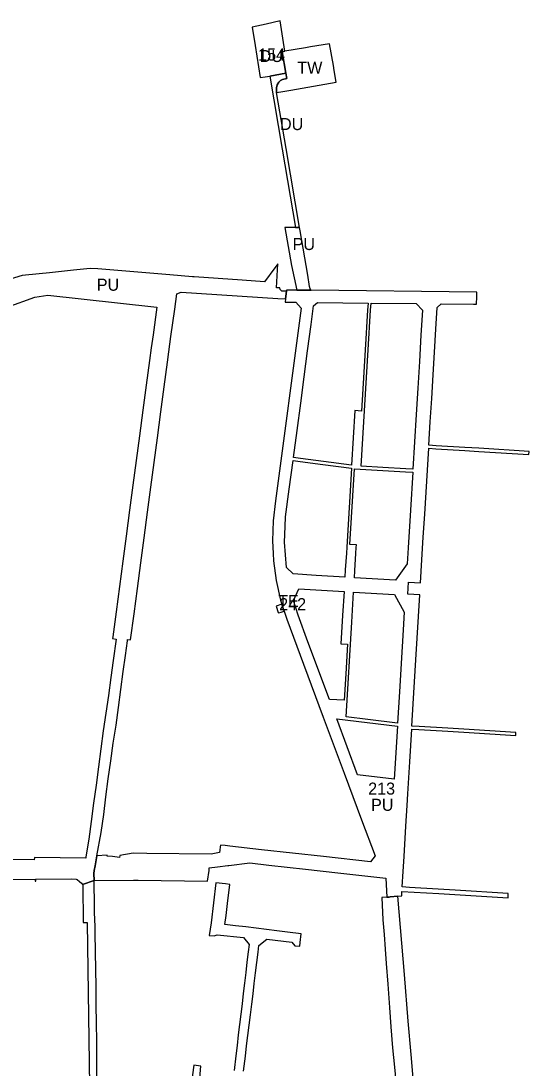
# Model space of a CAD drawing. Extents: x -521047 to -518054, y -1194945 to -1189555.
# Drawn here: x -519638 to -519216, y -1191621 to -1190751 of the extents above; entities that cross this region are included whole.
import ezdxf

# ---------------------------------------------------------------- set-up
doc = ezdxf.new("R2010")
doc.units = 0
for name, color, linetype in [('90310013', 7, 'Continuous'), ('90310023', 7, 'Continuous'), ('90390013', 7, 'Continuous'), ('90400023', 7, 'Continuous'), ('90450013', 7, 'Continuous'), ('90450023', 7, 'Continuous'), ('ID_navrh', 7, 'Continuous')]:
    doc.layers.add(name, color=color, linetype=linetype)

msp = doc.modelspace()

# ---------------------------------------------------------------- linework, layer by layer
at = {"layer": '90310013'}
msp.add_lwpolyline([(-519425.9, -1190810.59), (-519426, -1190810.03), (-519426.07, -1190806.55), (-519425.43, -1190804.16), (-519424.12, -1190802.05), (-519422.73, -1190800.6), (-519421.01, -1190799.59), (-519417.51, -1190798.76), (-519418.25, -1190794.59), (-519427.06, -1190796.08), (-519431.49, -1190796.83), (-519421.19, -1190857.53), (-519410.13, -1190922.68), (-519406.86, -1190922.67), (-519418.01, -1190857.09), (-519425.9, -1190810.59)], dxfattribs=at)
at = {"layer": '90310023'}
msp.add_lwpolyline([(-519431.49, -1190796.83), (-519427.06, -1190796.08), (-519418.25, -1190794.59), (-519421.35, -1190776.66), (-519419.09, -1190776.27), (-519423.08, -1190751.07), (-519434.67, -1190753.64), (-519446.26, -1190756.2), (-519443.82, -1190771.36), (-519439.5, -1190798.18), (-519435.5, -1190797.51), (-519431.49, -1190796.83)], dxfattribs=at)
at = {"layer": '90390013'}
msp.add_lwpolyline([(-519425.9, -1190810.59), (-519420.82, -1190809.69), (-519415.74, -1190808.8), (-519413.98, -1190808.49), (-519376.41, -1190801.97), (-519378.08, -1190792.18), (-519378.78, -1190788), (-519381.92, -1190770.01), (-519397.85, -1190772.66), (-519402.04, -1190773.36), (-519419.09, -1190776.27), (-519421.35, -1190776.66), (-519418.25, -1190794.59), (-519417.51, -1190798.76), (-519421.01, -1190799.59), (-519422.73, -1190800.6), (-519424.12, -1190802.05), (-519425.43, -1190804.16), (-519426.07, -1190806.55), (-519426, -1190810.03), (-519425.9, -1190810.59)], dxfattribs=at)
at = {"layer": '90400023'}
msp.add_lwpolyline([(-519421.48, -1191235.61), (-519426.25, -1191237.12), (-519424.56, -1191242.44), (-519424.44, -1191242.84), (-519421.98, -1191242.06), (-519419.67, -1191241.33), (-519420.1, -1191239.99), (-519421.46, -1191235.67), (-519421.48, -1191235.61)], dxfattribs=at)
at = {"layer": '90450013'}
for points in [[(-519419.2, -1190922.7), (-519413.53, -1190954.2), (-519409.21, -1190974.7), (-519397.29, -1190974.84), (-519398.04, -1190973.7), (-519398.51, -1190971.76), (-519400.11, -1190962.39), (-519406.39, -1190925.44), (-519406.86, -1190922.67), (-519410.13, -1190922.68), (-519414.66, -1190922.69), (-519419.2, -1190922.7)], [(-519417.75, -1190975.6), (-519421.6, -1190975.48), (-519423.05, -1190974.12), (-519423.35, -1190972.89), (-519426.07, -1190972.68), (-519424.76, -1190952.81), (-519427.27, -1190956.19), (-519435.92, -1190967.84), (-519454.45, -1190966.5), (-519474.45, -1190965.06), (-519494.45, -1190963.62), (-519495.64, -1190963.53), (-519514.45, -1190962), (-519534.46, -1190960.37), (-519554.46, -1190958.75), (-519574.46, -1190957.12), (-519580.63, -1190956.62), (-519594.46, -1190958.09), (-519614.46, -1190960.23), (-519634.45, -1190962.36), (-519637.19, -1190962.65), (-519654.44, -1190967.68)], [(-519734.08, -1191464.3), (-519626.5, -1191463.94), (-519626.5, -1191465.57), (-519625.81, -1191465.57), (-519625.82, -1191463.94), (-519595.86, -1191463.83), (-519592.36, -1191464.04), (-519591.42, -1191464.38), (-519589.46, -1191465.93), (-519587.99, -1191467.28), (-519586.99, -1191468.38), (-519577.51, -1191465.05), (-519577.64, -1191459.18), (-519577.4, -1191456.82), (-519576.66, -1191452.79), (-519575.16, -1191444.67), (-519571.58, -1191425.3), (-519569.46, -1191410.24), (-519567.75, -1191395.5), (-519565.7, -1191380.6), (-519563.45, -1191365.79), (-519561.62, -1191351.05), (-519559.21, -1191335.98), (-519557.24, -1191321.36), (-519555.15, -1191306.5), (-519553.19, -1191291.45), (-519551.46, -1191278.14), (-519549.81, -1191265.9), (-519549.65, -1191264.77), (-519547.09, -1191265.09), (-519544.25, -1191243.58), (-519541.47, -1191222.48), (-519538.69, -1191201.28), (-519535.92, -1191180.56), (-519533.06, -1191159.12), (-519530.29, -1191138.35), (-519527.54, -1191117.76), (-519524.82, -1191097.41), (-519521.95, -1191075.91), (-519519.18, -1191055.12), (-519516.44, -1191034.58), (-519515.29, -1191025.95), (-519513.6, -1191013.34), (-519510.54, -1190990.37), (-519508.85, -1190977.63), (-519505.2, -1190976.39), (-519424.9, -1190981.51), (-519418.57, -1190981.92), (-519417.75, -1190975.6)], [(-519649.73, -1190988.71), (-519626.59, -1190980.56), (-519615.78, -1190978.97), (-519588.06, -1190981.97), (-519525.44, -1190988.75), (-519528.51, -1191011.75), (-519529.95, -1191022.61), (-519531.36, -1191033.18), (-519534.1, -1191053.67), (-519536.85, -1191074.32), (-519539.71, -1191095.78), (-519542.44, -1191116.24), (-519543.82, -1191126.59), (-519545.18, -1191136.77), (-519547.94, -1191157.45), (-519550.81, -1191178.95), (-519553.58, -1191199.76), (-519556.38, -1191220.91), (-519559.17, -1191242.02), (-519561.89, -1191262.61), (-519562.09, -1191264.1), (-519559.08, -1191264.54), (-519561.72, -1191282.43), (-519563.63, -1191296.41), (-519565.38, -1191311.3), (-519567.65, -1191326.14), (-519569.89, -1191340.84), (-519571.87, -1191355.85), (-519573.82, -1191370.58), (-519575.84, -1191385.91), (-519577.81, -1191400.9), (-519579.89, -1191416.11), (-519581.9, -1191430.86), (-519584.36, -1191445.56), (-519584.29, -1191446.5), (-519626.81, -1191445.94), (-519627.09, -1191448.06), (-519657.04, -1191447.59)], [(-519575.11, -1191628.65), (-519575.26, -1191613.61), (-519575.26, -1191598.56), (-519575.45, -1191583.57), (-519575.65, -1191568.52), (-519575.75, -1191553.53), (-519575.99, -1191538.83), (-519576.22, -1191524.54), (-519576.49, -1191508.37), (-519576.64, -1191503.42), (-519577, -1191491.8), (-519577.15, -1191487.01), (-519577.51, -1191465.05), (-519586.99, -1191468.38), (-519586.83, -1191468.84), (-519586.55, -1191499.99), (-519583.09, -1191499.99), (-519580.83, -1191674.78)], [(-519453.36, -1191623.48), (-519451.82, -1191611.01), (-519450.78, -1191602.53), (-519449.7, -1191593.83), (-519448.57, -1191585.21), (-519447.62, -1191576.63), (-519446.55, -1191567.85), (-519445.5, -1191559.25), (-519444.45, -1191550.62), (-519443.39, -1191541.92), (-519442.33, -1191533.25), (-519441.27, -1191524.61), (-519440.6, -1191519.15), (-519433.91, -1191513.92), (-519413.38, -1191516.41), (-519410.68, -1191519.29), (-519406.71, -1191519.74), (-519406.35, -1191516.56), (-519405.54, -1191509.38), (-519416.85, -1191507.99), (-519425.59, -1191506.91), (-519434.21, -1191505.85), (-519442.74, -1191504.8), (-519451.47, -1191503.72), (-519460.11, -1191502.66), (-519468.8, -1191501.59), (-519467.9, -1191494.14), (-519466.69, -1191484.19), (-519464.87, -1191468.3), (-519468.24, -1191467.91), (-519476.39, -1191466.96), (-519480.11, -1191500.2), (-519481.79, -1191510.66), (-519477.82, -1191511.18), (-519475.17, -1191510.14), (-519453.49, -1191512.38), (-519448.78, -1191518.39), (-519449.49, -1191524.35), (-519450.51, -1191532.95), (-519451.54, -1191541.66), (-519452.56, -1191550.28), (-519453.59, -1191558.94), (-519454.62, -1191567.56), (-519455.64, -1191576.17), (-519456.67, -1191584.81), (-519457.69, -1191593.41), (-519458.72, -1191602.1), (-519459.75, -1191610.77), (-519461.19, -1191622.93)], [(-519309.03, -1191672.4), (-519314.27, -1191609.51), (-519316.54, -1191582.06), (-519319.78, -1191543.27), (-519325.22, -1191478.24), (-519331.7, -1191478.8), (-519332.56, -1191478.87), (-519333.28, -1191478.93), (-519334.48, -1191479.02), (-519338.54, -1191479.34), (-519337.61, -1191497.89), (-519336.71, -1191510.02), (-519335.82, -1191522.07), (-519334.94, -1191533.93), (-519333.66, -1191551.29), (-519332.23, -1191570.65), (-519331.04, -1191586.75), (-519329.6, -1191604.2), (-519327.99, -1191620.23), (-519326.26, -1191637.52)], [(-519491.4, -1191649.03), (-519488.74, -1191619.37), (-519494.72, -1191618.59), (-519498.55, -1191646.53)]]:
    msp.add_lwpolyline(points, dxfattribs=at)
at = {"layer": '90450023'}
for points in [[(-519233.5, -1191475.79), (-519277.54, -1191473.14), (-519291.64, -1191472.29), (-519315.59, -1191470.85), (-519321.58, -1191470.48), (-519320.82, -1191457.76), (-519320.06, -1191445.13), (-519318.53, -1191419.83), (-519317.5, -1191402.75), (-519316.93, -1191393.15), (-519315.32, -1191366.47), (-519313.69, -1191339.37), (-519307.7, -1191339.73), (-519283.74, -1191341.17), (-519270.52, -1191341.97), (-519227.35, -1191344.57), (-519227.23, -1191342.07), (-519270.38, -1191339.47), (-519283.59, -1191338.68), (-519307.55, -1191337.24), (-519313.54, -1191336.88), (-519312.43, -1191318.46), (-519311.32, -1191300.09), (-519310.22, -1191281.73), (-519309.14, -1191263.76), (-519308.05, -1191245.79), (-519306.97, -1191227.82), (-519316.95, -1191227.22), (-519316.35, -1191217.24), (-519306.37, -1191217.84), (-519305.23, -1191198.83), (-519304.09, -1191179.86), (-519302.94, -1191160.9), (-519301.84, -1191142.63), (-519300.74, -1191124.36), (-519299.64, -1191106.09), (-519293.65, -1191106.46), (-519269.7, -1191107.9), (-519258.03, -1191108.6), (-519216.41, -1191111.11), (-519216.29, -1191108.61), (-519257.89, -1191106.1), (-519269.55, -1191105.4), (-519293.5, -1191103.96), (-519299.49, -1191103.6), (-519298.32, -1191084.03), (-519297.14, -1191064.57), (-519295.97, -1191045.1), (-519294.83, -1191026.14), (-519293.69, -1191007.17), (-519292.6, -1190989.16), (-519289.31, -1190986.09), (-519262.38, -1190986.4), (-519259.89, -1190986.43), (-519259.67, -1190980.24), (-519259.53, -1190976.44), (-519397.29, -1190974.84), (-519409.21, -1190974.7), (-519417.62, -1190974.6), (-519417.66, -1190974.95), (-519417.58, -1190975.61), (-519417.75, -1190975.6), (-519418.57, -1190981.92), (-519418.92, -1190984.59), (-519412.96, -1190984.66), (-519411.43, -1190984.67), (-519409.91, -1190984.69), (-519405.56, -1190989.71), (-519426.73, -1191149.73), (-519428.73, -1191166.25), (-519429.31, -1191182.88), (-519428.77, -1191193.5), (-519428.47, -1191199.49), (-519426.21, -1191215.98), (-519422.56, -1191232.21), (-519421.48, -1191235.61), (-519421.46, -1191235.67), (-519420.1, -1191239.99), (-519419.67, -1191241.33), (-519417.54, -1191248.08), (-519403.63, -1191285.31), (-519387.2, -1191329.32), (-519369.81, -1191375.88), (-519355.34, -1191414.63), (-519344.11, -1191444.69), (-519347.98, -1191449.64), (-519386.94, -1191445.28), (-519412.78, -1191442.38), (-519438.52, -1191439.5), (-519464.69, -1191436.57), (-519468.64, -1191436.13), (-519472.58, -1191435.69), (-519472.77, -1191437.09), (-519473.18, -1191440.03), (-519473.41, -1191441.72), (-519480.3, -1191443.11), (-519533.77, -1191442.8), (-519544.94, -1191442.33), (-519556.21, -1191444.23), (-519556.39, -1191445.91), (-519562.18, -1191445.17), (-519566.72, -1191444.78), (-519566.62, -1191443.98), (-519575.16, -1191444.67), (-519576.66, -1191452.79), (-519577.4, -1191456.82), (-519577.64, -1191459.18), (-519577.51, -1191465.05), (-519544.61, -1191464.84), (-519540.95, -1191464.89), (-519483.25, -1191465.69), (-519481.98, -1191456.8), (-519481.78, -1191454.44), (-519474.91, -1191453.7), (-519466.53, -1191452.71), (-519465.48, -1191452.58), (-519448.03, -1191450.51), (-519432.28, -1191452.28), (-519402.01, -1191455.67), (-519374.98, -1191458.69), (-519335.08, -1191463.16), (-519334.48, -1191479.02), (-519333.28, -1191478.93), (-519332.56, -1191478.87), (-519331.7, -1191478.8), (-519325.22, -1191478.24), (-519322.03, -1191477.97), (-519321.8, -1191474.15), (-519291.33, -1191476), (-519233.67, -1191479.5), (-519233.5, -1191475.79)], [(-519387.1, -1191117.04), (-519405.94, -1191114.55), (-519411.89, -1191113.76), (-519408.9, -1191091.16), (-519405.91, -1191068.61), (-519403.03, -1191046.8), (-519400.14, -1191024.99), (-519397.25, -1191003.18), (-519395.22, -1190987.84), (-519391.87, -1190984.9), (-519349.98, -1190985.39), (-519350.34, -1190991.38), (-519351.18, -1191005.37), (-519351.49, -1191010.37), (-519355.39, -1191075.29), (-519360.86, -1191074.57), (-519362.23, -1191097.34), (-519363.6, -1191120.15), (-519387.1, -1191117.04)], [(-519337.67, -1191121.99), (-519355.64, -1191120.91), (-519348.98, -1191010.4), (-519348.68, -1191005.4), (-519347.84, -1190991.41), (-519347.48, -1190985.42), (-519309.96, -1190985.85), (-519304.76, -1190991.38), (-519306.01, -1191012.14), (-519307.33, -1191034.1), (-519308.65, -1191056.06), (-519309.98, -1191078.02), (-519311.34, -1191100.73), (-519312.71, -1191123.49), (-519318.7, -1191123.13), (-519337.67, -1191121.99)], [(-519387.43, -1191119.47), (-519363.75, -1191122.6), (-519367.7, -1191188.1), (-519368, -1191193.09), (-519368.84, -1191207.07), (-519369.2, -1191213.06), (-519393.15, -1191211.62), (-519412.25, -1191210.47), (-519417.68, -1191205.18), (-519419.26, -1191184.09), (-519418.72, -1191170.93), (-519418.4, -1191162.95), (-519415.36, -1191139.98), (-519412.21, -1191116.19), (-519406.26, -1191116.98), (-519387.43, -1191119.47)], [(-519359.71, -1191188.58), (-519359.57, -1191186.24), (-519365.06, -1191185.91), (-519361.27, -1191123.02), (-519337.82, -1191124.43), (-519318.85, -1191125.58), (-519312.86, -1191125.94), (-519314.75, -1191157.38), (-519316.65, -1191188.82), (-519317.45, -1191202.15), (-519327.17, -1191215.59), (-519361.21, -1191213.54), (-519360.85, -1191207.55), (-519360.01, -1191193.57), (-519359.71, -1191188.58)], [(-519368.53, -1191293.54), (-519369.85, -1191315.4), (-519381.99, -1191314.67), (-519399.84, -1191266.86), (-519408.14, -1191244.64), (-519411.75, -1191232.59), (-519407.56, -1191222.77), (-519369.92, -1191225.04), (-519371.12, -1191245), (-519372.54, -1191268.51), (-519367.05, -1191268.84), (-519368.53, -1191293.54)], [(-519350.27, -1191331.3), (-519368.17, -1191329.12), (-519363.44, -1191250.47), (-519363.14, -1191245.48), (-519361.93, -1191225.52), (-519327.89, -1191227.57), (-519319.85, -1191242.08), (-519320.75, -1191257), (-519322.43, -1191284.95), (-519323.85, -1191308.41), (-519325.41, -1191334.34), (-519350.27, -1191331.3)], [(-519328.22, -1191381.04), (-519358.62, -1191377.27), (-519376.01, -1191330.68), (-519325.56, -1191336.84), (-519328.22, -1191381.04)]]:
    msp.add_lwpolyline(points, dxfattribs=at)

# ---------------------------------------------------------------- texts
at = {"layer": '90310013'}
msp.add_text('DU', height=10, rotation=360, dxfattribs=at).set_placement((-519423.08, -1190841.74))
at = {"layer": '90310023'}
msp.add_text('DU', height=10, rotation=360, dxfattribs=at).set_placement((-519439.98, -1190785.2))
at = {"layer": '90390013'}
msp.add_text('TW', height=10, rotation=360, dxfattribs=at).set_placement((-519408.71, -1190794.94))
at = {"layer": '90400023'}
msp.add_text('TE', height=10, rotation=360, dxfattribs=at).set_placement((-519424.62, -1191237.97))
at = {"layer": '90450013'}
for p in [(-519412.6, -1190941.38), (-519575.18, -1190975.22)]:
    msp.add_text('PU', height=10, rotation=0, dxfattribs=at).set_placement(p)
at = {"layer": '90450023'}
msp.add_text('PU', height=10, rotation=0, dxfattribs=at).set_placement((-519347.45, -1191407.23))
at = {"layer": 'ID_navrh'}
for s, rotation, p in [('154', 360, (-519441.19, -1190783.96)), ('242', 360, (-519423.75, -1191240.55)), ('213', 0, (-519349.86, -1191393.75))]:
    msp.add_text(s, height=10, rotation=rotation, dxfattribs=at).set_placement(p)

doc.saveas('drawing.dxf')
